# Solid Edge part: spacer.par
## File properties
Author: Binay
Template: sync ansi part.par
Last saved by: TIET
Revision: 8
Application: Solid Edge
Accuracy: 0.990
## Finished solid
Body 1: solid body, 4 faces, 4 edges, 0 vertices.
  Faces by surface: cylinder 2, plane 2
  Edges by curve: circle 4
Bounding box of the edges (mm): 31.750 x 31.750 x 34.925, from (-23.8946, 129.8949, -17.4625) to (7.8554, 161.6449, 17.4625).
Cylindrical faces by radius (mm): R12.7 x1, R15.875 x1
Planar faces by outward normal: +z 1, -z 1
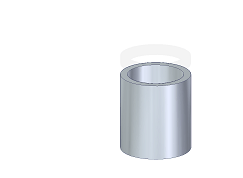
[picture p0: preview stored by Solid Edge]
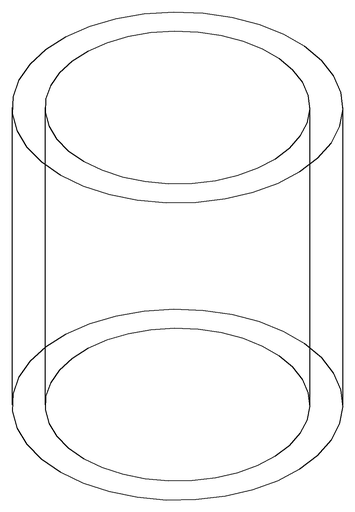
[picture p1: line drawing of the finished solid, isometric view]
